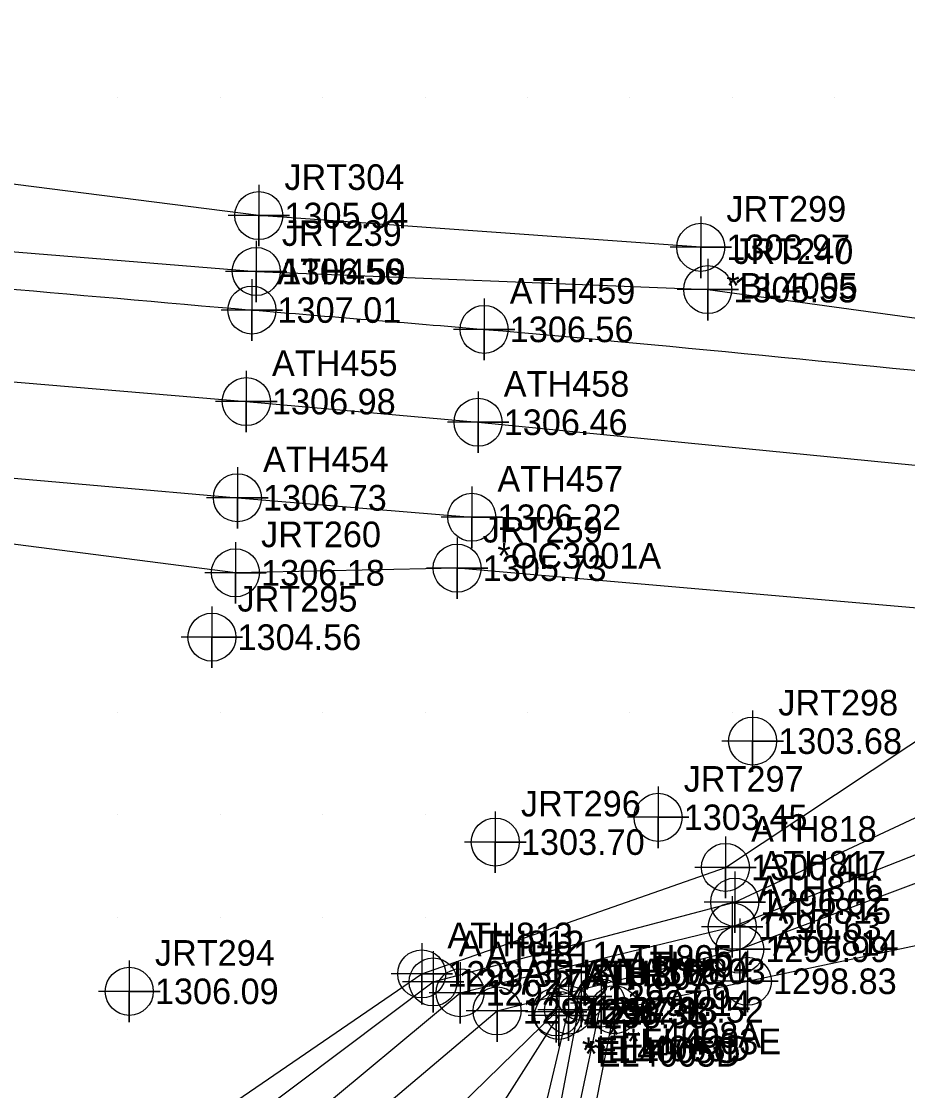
# Model space of a CAD drawing. Extents: x 1234484 to 1235382, y 695050 to 695510.
# Drawn here: x 1234800.6 to 1234887.1, y 695263.1 to 695367.4 of the extents above; entities that cross this region are included whole.
import ezdxf

# ---------------------------------------------------------------- set-up
doc = ezdxf.new("R2010")
doc.units = 0
for name, color, linetype in [('Exist DTM Breakline', 7, 'Continuous'), ('Exist DTM Breakline Cogo Comment', 7, 'Continuous'), ('Exist DTM Breakline Cogo Elevation', 7, 'Continuous'), ('Exist DTM Breakline Cogo Number', 7, 'Continuous'), ('Exist DTM Breakline Cogo Point CELL', 7, 'Continuous'), ('Exist DTM Breakline Underwater', 7, 'Continuous'), ('Exist DTM Crownline', 7, 'Continuous'), ('Exist DTM Crownline Cogo Elevation', 7, 'Continuous'), ('Exist DTM Crownline Cogo Number', 7, 'Continuous'), ('Exist DTM Crownline Cogo Point CELL', 7, 'Continuous'), ('Exist DTM Drainline Cogo Comment', 7, 'Continuous'), ('Exist DTM Drainline Cogo Elevation', 7, 'Continuous'), ('Exist DTM Drainline Cogo Number', 7, 'Continuous'), ('Exist DTM Drainline Cogo Point CELL', 7, 'Continuous'), ('Exist DTM QL2 LIDAR Elevation Point', 7, 'Continuous'), ('Exist DTM Regular Point CELL', 7, 'Continuous'), ('Exist DTM Regular Point Cogo Elevation', 7, 'Continuous'), ('Exist DTM Regular Point Cogo Number', 7, 'Continuous'), ('Exist DTM Regular Point Underwater CELL', 7, 'Continuous'), ('Exist DTM Regular Point Underwater Cogo Comment', 7, 'Continuous'), ('Exist DTM Regular Point Underwater Cogo Elevation', 7, 'Continuous'), ('Exist DTM Regular Point Underwater Cogo Number', 7, 'Continuous'), ('Exist Hydro Stream or Body of Water', 7, 'Continuous'), ('Exist Roads EOP', 7, 'Continuous'), ('Exist Roads EOP Cogo Comment', 7, 'Continuous'), ('Exist Roads EOP Cogo Elevation', 7, 'Continuous'), ('Exist Roads EOP Cogo Number', 7, 'Continuous'), ('Exist Roads EOP Cogo Point CELL', 7, 'Continuous'), ('Old_Level_50', 7, 'Continuous')]:
    doc.layers.add(name, color=color, linetype=linetype)

msp = doc.modelspace()

# ---------------------------------------------------------------- linework, layer by layer
at = {"layer": 'Exist DTM Breakline'}
for points in [[(1234866.911, 695345.376), (1234823.763, 695348.478), (1234767.785, 695355.619), (1234719.498, 695356.897), (1234661.167, 695363.182), (1234623.376, 695365.3), (1234610.221, 695366.341), (1234608.231, 695369.759), (1234607.001, 695375.947)], [(1234608.156, 695366.132), (1234620.219, 695363.657), (1234657.83, 695357.954), (1234716.822, 695351.015), (1234771.134, 695347.284), (1234823.515, 695343.018), (1234867.598, 695341.251), (1234907.686, 695335.753), (1234932.171, 695332.602)], [(1234900.418, 695309.093), (1234843.128, 695314.065), (1234821.486, 695313.61), (1234768.142, 695320.476), (1234713.4, 695324.265), (1234656.708, 695330.451), (1234602.942, 695334.287)], [(1234766.2, 695216.412), (1234807.252, 695252.276), (1234839.673, 695274.467), (1234869.326, 695284.86), (1234890.801, 695299.09), (1234911.196, 695302.79), (1234918.594, 695307.818)], [(1234840.371, 695218.638), (1234853.212, 695244.202), (1234858.487, 695270.963), (1234871.461, 695273.745), (1234897.697, 695279.312), (1234915.088, 695274.445), (1234918.81, 695282.981)], [(1234773.364, 695206.653), (1234820.257, 695240.015), (1234835.082, 695253.487), (1234852.804, 695270.766)], [(1234830.712, 695227.716), (1234840.448, 695250.618), (1234853.055, 695270.415)]]:
    msp.add_lwpolyline(points, dxfattribs=at)
at = {"layer": 'Exist DTM Breakline Cogo Point CELL'}
for points in [[(1234823.763, 695351.478), (1234823.763, 695345.478), (1234823.763, 695348.478), (1234826.763, 695348.478), (1234820.763, 695348.478)], [(1234866.911, 695348.376), (1234866.911, 695342.376), (1234866.911, 695345.376), (1234869.911, 695345.376), (1234863.911, 695345.376)], [(1234823.515, 695346.018), (1234823.515, 695340.018), (1234823.515, 695343.018), (1234826.515, 695343.018), (1234820.515, 695343.018)], [(1234867.598, 695344.251), (1234867.598, 695338.251), (1234867.598, 695341.251), (1234870.598, 695341.251), (1234864.598, 695341.251)], [(1234843.128, 695317.065), (1234843.128, 695311.065), (1234843.128, 695314.065), (1234846.128, 695314.065), (1234840.128, 695314.065)], [(1234821.486, 695316.61), (1234821.486, 695310.61), (1234821.486, 695313.61), (1234824.486, 695313.61), (1234818.486, 695313.61)], [(1234869.326, 695287.86), (1234869.326, 695281.86), (1234869.326, 695284.86), (1234872.326, 695284.86), (1234866.326, 695284.86)], [(1234839.673, 695277.467), (1234839.673, 695271.467), (1234839.673, 695274.467), (1234842.673, 695274.467), (1234836.673, 695274.467)], [(1234871.461, 695276.745), (1234871.461, 695270.745), (1234871.461, 695273.745), (1234874.461, 695273.745), (1234868.461, 695273.745)], [(1234852.804, 695273.766), (1234852.804, 695267.766), (1234852.804, 695270.766), (1234855.804, 695270.766), (1234849.804, 695270.766)], [(1234853.055, 695273.415), (1234853.055, 695267.415), (1234853.055, 695270.415), (1234856.055, 695270.415), (1234850.055, 695270.415)], [(1234858.487, 695273.963), (1234858.487, 695267.963), (1234858.487, 695270.963), (1234861.487, 695270.963), (1234855.487, 695270.963)]]:
    msp.add_lwpolyline(points, dxfattribs=at)
for centre in [(1234823.763, 695348.478), (1234866.911, 695345.376), (1234823.515, 695343.018), (1234867.598, 695341.251), (1234821.486, 695313.61), (1234843.128, 695314.065), (1234869.326, 695284.86), (1234839.673, 695274.467), (1234871.461, 695273.745), (1234852.804, 695270.766), (1234858.487, 695270.963), (1234853.055, 695270.415)]:
    msp.add_circle(centre, 2.344, dxfattribs=at)
at = {"layer": 'Exist DTM Breakline Underwater'}
msp.add_lwpolyline([(1234766.421, 695209.389), (1234812.885, 695247.237), (1234843.411, 695272.621), (1234869.986, 695279.055), (1234895.378, 695289.036), (1234916.238, 695295.408), (1234934.131, 695306.081), (1234961.466, 695329.617), (1234991.436, 695342.664), (1235009.265, 695346.147), (1235040.352, 695365.623), (1235072.367, 695380.008), (1235092.174, 695396.335)], dxfattribs=at)
at = {"layer": 'Exist DTM Crownline'}
msp.add_lwpolyline([(1234511.603, 695359.057), (1234605.73, 695349.422), (1234657.657, 695344.297), (1234715.146, 695339.445), (1234769.335, 695334.825), (1234822.546, 695330.321), (1234845.176, 695328.304), (1234903.738, 695322.57)], dxfattribs=at)
at = {"layer": 'Exist DTM Crownline Cogo Point CELL'}
for points in [[(1234822.546, 695333.321), (1234822.546, 695327.321), (1234822.546, 695330.321), (1234825.546, 695330.321), (1234819.546, 695330.321)], [(1234845.176, 695331.304), (1234845.176, 695325.304), (1234845.176, 695328.304), (1234848.176, 695328.304), (1234842.176, 695328.304)]]:
    msp.add_lwpolyline(points, dxfattribs=at)
for centre in [(1234822.546, 695330.321), (1234845.176, 695328.304)]:
    msp.add_circle(centre, 2.344, dxfattribs=at)
at = {"layer": 'Exist DTM Drainline Cogo Point CELL'}
for points in [[(1234870.231, 695284.467), (1234870.231, 695278.467), (1234870.231, 695281.467), (1234873.231, 695281.467), (1234867.231, 695281.467)], [(1234870.723, 695279.867), (1234870.723, 695273.867), (1234870.723, 695276.867), (1234873.723, 695276.867), (1234867.723, 695276.867)], [(1234840.783, 695276.683), (1234840.783, 695270.683), (1234840.783, 695273.683), (1234843.783, 695273.683), (1234837.783, 695273.683)], [(1234857.192, 695274.621), (1234857.192, 695268.621), (1234857.192, 695271.621), (1234860.192, 695271.621), (1234854.192, 695271.621)], [(1234847.025, 695273.849), (1234847.025, 695267.849), (1234847.025, 695270.849), (1234850.025, 695270.849), (1234844.025, 695270.849)], [(1234854.006, 695273.943), (1234854.006, 695267.943), (1234854.006, 695270.943), (1234857.006, 695270.943), (1234851.006, 695270.943)]]:
    msp.add_lwpolyline(points, dxfattribs=at)
for centre in [(1234870.231, 695281.467), (1234870.723, 695276.867), (1234840.783, 695273.683), (1234847.025, 695270.849), (1234854.006, 695270.943), (1234857.192, 695271.621)]:
    msp.add_circle(centre, 2.344, dxfattribs=at)
at = {"layer": 'Exist DTM QL2 LIDAR Elevation Point'}
for p, q in [((1234810, 695360), (1234810, 695360)), ((1234820, 695360), (1234820, 695360)), ((1234830, 695360), (1234830, 695360)), ((1234840, 695360), (1234840, 695360)), ((1234850, 695360), (1234850, 695360)), ((1234860, 695360), (1234860, 695360)), ((1234870, 695360), (1234870, 695360)), ((1234880, 695360), (1234880, 695360)), ((1234870, 695350), (1234870, 695350)), ((1234880, 695350), (1234880, 695350)), ((1234810, 695300), (1234810, 695300)), ((1234820, 695300), (1234820, 695300)), ((1234830, 695300), (1234830, 695300)), ((1234840, 695300), (1234840, 695300)), ((1234850, 695300), (1234850, 695300)), ((1234860, 695300), (1234860, 695300)), ((1234870, 695300), (1234870, 695300)), ((1234880, 695300), (1234880, 695300)), ((1234810, 695290), (1234810, 695290)), ((1234820, 695290), (1234820, 695290)), ((1234830, 695290), (1234830, 695290)), ((1234840, 695290), (1234840, 695290)), ((1234850, 695290), (1234850, 695290)), ((1234860, 695290), (1234860, 695290)), ((1234810, 695280), (1234810, 695280)), ((1234820, 695280), (1234820, 695280)), ((1234830, 695280), (1234830, 695280)), ((1234840, 695280), (1234840, 695280)), ((1234810, 695270), (1234810, 695270))]:
    msp.add_line(p, q, dxfattribs=at)
at = {"layer": 'Exist DTM Regular Point CELL'}
for points in [[(1234819.185, 695310.328), (1234819.185, 695304.328), (1234819.185, 695307.328), (1234822.185, 695307.328), (1234816.185, 695307.328)], [(1234871.979, 695300.185), (1234871.979, 695294.185), (1234871.979, 695297.185), (1234874.979, 695297.185), (1234868.979, 695297.185)], [(1234862.747, 695292.746), (1234862.747, 695286.746), (1234862.747, 695289.746), (1234865.747, 695289.746), (1234859.747, 695289.746)], [(1234846.854, 695290.331), (1234846.854, 695284.331), (1234846.854, 695287.331), (1234849.854, 695287.331), (1234843.854, 695287.331)], [(1234811.12, 695275.763), (1234811.12, 695269.763), (1234811.12, 695272.763), (1234814.12, 695272.763), (1234808.12, 695272.763)]]:
    msp.add_lwpolyline(points, dxfattribs=at)
for centre in [(1234819.185, 695307.328), (1234871.979, 695297.185), (1234862.747, 695289.746), (1234846.854, 695287.331), (1234811.12, 695272.763)]:
    msp.add_circle(centre, 2.344, dxfattribs=at)
at = {"layer": 'Exist DTM Regular Point Underwater CELL'}
for points in [[(1234869.986, 695282.055), (1234869.986, 695276.055), (1234869.986, 695279.055), (1234872.986, 695279.055), (1234866.986, 695279.055)], [(1234843.411, 695275.621), (1234843.411, 695269.621), (1234843.411, 695272.621), (1234846.411, 695272.621), (1234840.411, 695272.621)], [(1234855.246, 695275.274), (1234855.246, 695269.274), (1234855.246, 695272.274), (1234858.246, 695272.274), (1234852.246, 695272.274)]]:
    msp.add_lwpolyline(points, dxfattribs=at)
for centre in [(1234869.986, 695279.055), (1234843.411, 695272.621), (1234855.246, 695272.274)]:
    msp.add_circle(centre, 2.344, dxfattribs=at)
at = {"layer": 'Exist Hydro Stream or Body of Water'}
for points in [[(1234766.439, 695214.543), (1234809.451, 695250.146), (1234840.783, 695273.683), (1234870.231, 695281.467), (1234894.384, 695292.767), (1234915.014, 695298.345), (1234929.933, 695306.511), (1234953.845, 695329.807), (1234986.204, 695341.472), (1235008.526, 695348.915), (1235037.336, 695368.653), (1235069.491, 695383.302), (1235088.448, 695400.861)], [(1234770.872, 695207.044), (1234815.763, 695244.4), (1234847.025, 695270.849), (1234870.723, 695276.867), (1234895.944, 695286.356), (1234916.555, 695293.487), (1234933.154, 695302.663)], [(1234835.336, 695223.655), (1234848.212, 695246.579), (1234854.006, 695270.943)], [(1234838.142, 695220.308), (1234851.51, 695244.706), (1234857.192, 695271.621)]]:
    msp.add_lwpolyline(points, dxfattribs=at)
at = {"layer": 'Exist Roads EOP'}
msp.add_lwpolyline([(1234510.022, 695349.783), (1234546.237, 695345.927), (1234604.07, 695340.356), (1234657.035, 695335.026), (1234714.094, 695329.996), (1234768.395, 695325.598), (1234821.671, 695320.933), (1234844.56, 695319.029)], dxfattribs=at)
msp.add_spline([(1234605.599, 695398.165), (1234601.696, 695381.855), (1234613.593, 695357.692), (1234658.916, 695353.52), (1234716.264, 695348.291), (1234770.499, 695343.743), (1234823.09, 695339.258), (1234845.762, 695337.371), (1234903.754, 695331.785), (1234928.613, 695329.389)], degree=3, dxfattribs=at)
at = {"layer": 'Exist Roads EOP Cogo Point CELL'}
for points in [[(1234823.09, 695342.258), (1234823.09, 695336.258), (1234823.09, 695339.258), (1234826.09, 695339.258), (1234820.09, 695339.258)], [(1234845.762, 695340.371), (1234845.762, 695334.371), (1234845.762, 695337.371), (1234848.762, 695337.371), (1234842.762, 695337.371)], [(1234821.671, 695323.933), (1234821.671, 695317.933), (1234821.671, 695320.933), (1234824.671, 695320.933), (1234818.671, 695320.933)], [(1234844.56, 695322.029), (1234844.56, 695316.029), (1234844.56, 695319.029), (1234847.56, 695319.029), (1234841.56, 695319.029)]]:
    msp.add_lwpolyline(points, dxfattribs=at)
for centre in [(1234823.09, 695339.258), (1234845.762, 695337.371), (1234821.671, 695320.933), (1234844.56, 695319.029)]:
    msp.add_circle(centre, 2.344, dxfattribs=at)
at = {"layer": 'Old_Level_50'}
msp.add_lwpolyline([(1234836.619, 695222.333), (1234850.191, 695245.82), (1234855.246, 695272.274)], dxfattribs=at)

# ---------------------------------------------------------------- texts
at = {"layer": 'Exist DTM Breakline Cogo Comment'}
for s, p in [('*BL4005', (1234869.411, 695340.376)), ('*EL4005C', (1234855.304, 695265.766)), ('*EL4005D', (1234855.555, 695265.415))]:
    msp.add_text(s, height=2.5, dxfattribs=at).set_placement(p)
at = {"layer": 'Exist DTM Breakline Cogo Elevation'}
for s, p in [('1305.94', (1234826.263, 695347.228)), ('1303.97', (1234869.411, 695344.126)), ('1306.59', (1234826.015, 695341.768)), ('1305.55', (1234870.098, 695340.001)), ('1306.18', (1234823.986, 695312.36)), ('1305.73', (1234845.628, 695312.815)), ('1300.41', (1234871.826, 695283.61)), ('1299.35', (1234842.173, 695273.217)), ('1298.83', (1234873.961, 695272.495)), ('1298.31', (1234855.304, 695269.516)), ('1298.52', (1234860.987, 695269.713)), ('1298.35', (1234855.555, 695269.165))]:
    msp.add_text(s, height=2.5, dxfattribs=at).set_placement(p)
at = {"layer": 'Exist DTM Breakline Cogo Number'}
for s, p in [('JRT304', (1234826.263, 695350.978)), ('JRT299', (1234869.411, 695347.876)), ('JRT239', (1234826.015, 695345.518)), ('JRT240', (1234870.098, 695343.751)), ('JRT259', (1234845.628, 695316.565)), ('JRT260', (1234823.986, 695316.11)), ('ATH818', (1234871.826, 695287.36)), ('ATH813', (1234842.173, 695276.967)), ('ATH814', (1234873.961, 695276.245)), ('ATH808', (1234855.304, 695273.266)), ('ATH807', (1234855.555, 695272.915)), ('ATH803', (1234860.987, 695273.463))]:
    msp.add_text(s, height=2.5, dxfattribs=at).set_placement(p)
at = {"layer": 'Exist DTM Crownline Cogo Elevation'}
for s, p in [('1306.98', (1234825.046, 695329.071)), ('1306.46', (1234847.676, 695327.054))]:
    msp.add_text(s, height=2.5, dxfattribs=at).set_placement(p)
at = {"layer": 'Exist DTM Crownline Cogo Number'}
for s, p in [('ATH455', (1234825.046, 695332.821)), ('ATH458', (1234847.676, 695330.804))]:
    msp.add_text(s, height=2.5, dxfattribs=at).set_placement(p)
at = {"layer": 'Exist DTM Drainline Cogo Comment'}
for s, p in [('*EL4003E', (1234859.692, 695266.621)), ('*EL4003D', (1234856.506, 695265.943))]:
    msp.add_text(s, height=2.5, dxfattribs=at).set_placement(p)
at = {"layer": 'Exist DTM Drainline Cogo Elevation'}
for s, p in [('1296.62', (1234872.731, 695280.217)), ('1296.99', (1234873.223, 695275.617)), ('1297.27', (1234843.283, 695272.433)), ('1297.25', (1234849.525, 695269.599)), ('1297.13', (1234856.506, 695269.693)), ('1297.14', (1234859.692, 695270.371))]:
    msp.add_text(s, height=2.5, dxfattribs=at).set_placement(p)
at = {"layer": 'Exist DTM Drainline Cogo Number'}
for s, p in [('ATH817', (1234872.731, 695283.967)), ('ATH815', (1234873.223, 695279.367)), ('ATH812', (1234843.283, 695276.183)), ('ATH804', (1234859.692, 695274.121)), ('ATH810', (1234849.525, 695273.349)), ('ATH806', (1234856.506, 695273.443))]:
    msp.add_text(s, height=2.5, dxfattribs=at).set_placement(p)
at = {"layer": 'Exist DTM Regular Point Cogo Elevation'}
for s, p in [('1304.56', (1234821.685, 695306.078)), ('1303.68', (1234874.479, 695295.935)), ('1303.45', (1234865.247, 695288.496)), ('1303.70', (1234849.354, 695286.081)), ('1306.09', (1234813.62, 695271.513))]:
    msp.add_text(s, height=2.5, dxfattribs=at).set_placement(p)
at = {"layer": 'Exist DTM Regular Point Cogo Number'}
for s, p in [('JRT295', (1234821.685, 695309.828)), ('JRT298', (1234874.479, 695299.685)), ('JRT297', (1234865.247, 695292.246)), ('JRT296', (1234849.354, 695289.831)), ('JRT294', (1234813.62, 695275.263))]:
    msp.add_text(s, height=2.5, dxfattribs=at).set_placement(p)
at = {"layer": 'Exist DTM Regular Point Underwater Cogo Comment'}
msp.add_text('*EL4008A', height=2.5, dxfattribs=at).set_placement((1234857.746, 695267.274))
at = {"layer": 'Exist DTM Regular Point Underwater Cogo Elevation'}
for s, p in [('1296.63', (1234872.486, 695277.805)), ('1297.42', (1234845.911, 695271.371)), ('1297.09', (1234857.746, 695271.024))]:
    msp.add_text(s, height=2.5, dxfattribs=at).set_placement(p)
at = {"layer": 'Exist DTM Regular Point Underwater Cogo Number'}
for s, p in [('ATH816', (1234872.486, 695281.555)), ('ATH811', (1234845.911, 695275.121)), ('ATH805', (1234857.746, 695274.774))]:
    msp.add_text(s, height=2.5, dxfattribs=at).set_placement(p)
at = {"layer": 'Exist Roads EOP Cogo Comment'}
msp.add_text('*OC3001A', height=2.5, dxfattribs=at).set_placement((1234847.06, 695314.029))
at = {"layer": 'Exist Roads EOP Cogo Elevation'}
for s, p in [('1307.01', (1234825.59, 695338.008)), ('1306.56', (1234848.262, 695336.121)), ('1306.73', (1234824.171, 695319.683)), ('1306.22', (1234847.06, 695317.779))]:
    msp.add_text(s, height=2.5, dxfattribs=at).set_placement(p)
at = {"layer": 'Exist Roads EOP Cogo Number'}
for s, p in [('ATH456', (1234825.59, 695341.758)), ('ATH459', (1234848.262, 695339.871)), ('ATH454', (1234824.171, 695323.433)), ('ATH457', (1234847.06, 695321.529))]:
    msp.add_text(s, height=2.5, dxfattribs=at).set_placement(p)

doc.saveas('drawing.dxf')
